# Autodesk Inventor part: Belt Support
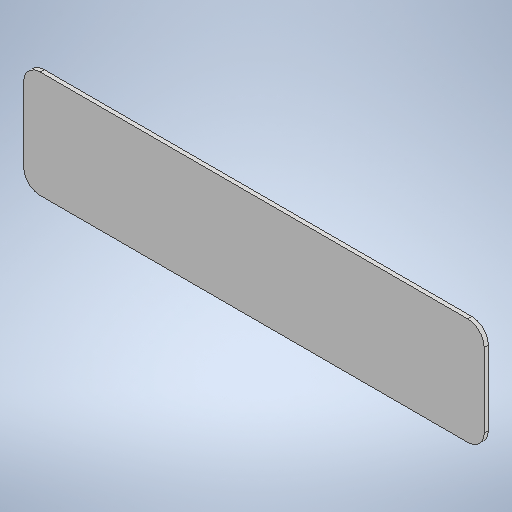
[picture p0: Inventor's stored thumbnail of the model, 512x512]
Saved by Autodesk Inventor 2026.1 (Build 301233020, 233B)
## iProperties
Created: 2026-10
Part Number: Belt Support
Material: Generic
Document SubType Name: Modeling
Designer: hp
Density: 1 g/cm^3
Appearance: Default
Author: hp
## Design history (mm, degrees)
sketch "Sketch1"
  geometry: L1 (0, 0)-(560, 0); L2 (560, 0)-(560, 130); L3 (560, 130)-(0, 130); L4 (0, 130)-(0, 0)
  constraints: 8 end point, 2 parallel, 1 horizontal, 1 perpendicular
  dimensions: "d0" = 560 distance of L3.end L2.end; "d1" = 130 distance of L2.end L1.end
extrude "Extrusion1" new body sketch "Sketch1" distance "d2" = 5; taper "d3" = 0 deg
fillet "Fillet1" dims "d4" = 20
body "Solid1"
